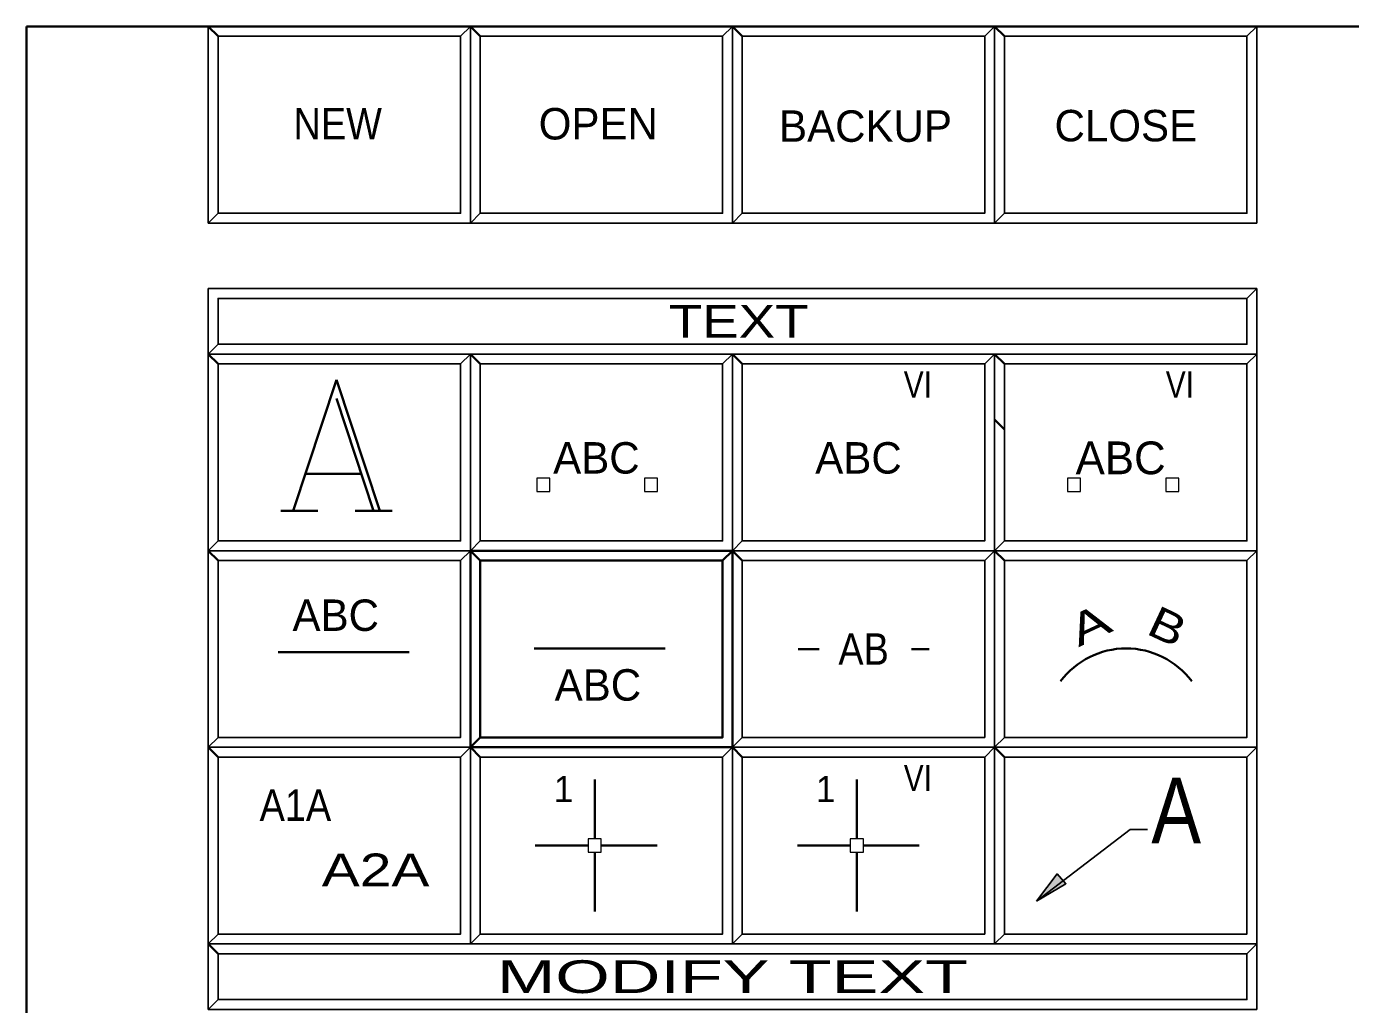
# Model space of a CAD drawing. Extents: x 95906.9 to 95918.9, y 90964.8 to 90972.9.
# Drawn here: x 95906.855 to 95908.876, y 90971.369 to 90972.862 of the extents above; entities that cross this region are included whole.
import ezdxf
from ezdxf.enums import TextEntityAlignment as Align

# ---------------------------------------------------------------- set-up
doc = ezdxf.new("R2010")
doc.units = 0
doc.header["$LTSCALE"] = 0.019
for name, color, linetype, lineweight in [('1', 7, 'Continuous', 25), ('11', 7, 'Continuous', 25), ('12', 7, 'Continuous', 25), ('17', 7, 'Continuous', 25), ('18', 7, 'Continuous', 25), ('2', 7, 'Continuous', 13), ('3', 7, 'Continuous', 25), ('4', 7, 'Continuous', 35), ('6', 7, 'Continuous', 35), ('7', 7, 'Continuous', 35)]:
    doc.layers.add(name, color=color, linetype=linetype, lineweight=lineweight)

msp = doc.modelspace()

# ---------------------------------------------------------------- hatches: boundary and pattern name
at = {"layer": '6'}
msp.add_hatch(color=256, dxfattribs=at).paths.add_polyline_path([(95908.3963, 90971.5268), (95908.4276, 90971.5686), (95908.4412, 90971.5534)])

# ---------------------------------------------------------------- linework, layer by layer
at = {"layer": '1'}
for points in [[(95907.1323, 90972.5617), (95907.5323, 90972.5617), (95907.5323, 90972.8617), (95907.1323, 90972.8617)], [(95907.5323, 90972.5617), (95907.9323, 90972.5617), (95907.9323, 90972.8617), (95907.5323, 90972.8617)], [(95907.9323, 90972.5617), (95908.3323, 90972.5617), (95908.3323, 90972.8617), (95907.9323, 90972.8617)], [(95908.3323, 90972.5617), (95908.7323, 90972.5617), (95908.7323, 90972.8617), (95908.3323, 90972.8617)], [(95907.1323, 90972.3617), (95908.7323, 90972.3617), (95908.7323, 90972.4617), (95907.1323, 90972.4617)], [(95907.1323, 90972.0617), (95907.5323, 90972.0617), (95907.5323, 90972.3617), (95907.1323, 90972.3617)], [(95907.5323, 90972.0617), (95907.9323, 90972.0617), (95907.9323, 90972.3617), (95907.5323, 90972.3617)], [(95907.9323, 90972.0617), (95908.3323, 90972.0617), (95908.3323, 90972.3617), (95907.9323, 90972.3617)], [(95908.3323, 90972.0617), (95908.7323, 90972.0617), (95908.7323, 90972.3617), (95908.3323, 90972.3617)], [(95907.1323, 90971.7617), (95907.5323, 90971.7617), (95907.5323, 90972.0617), (95907.1323, 90972.0617)], [(95907.5323, 90971.7617), (95907.9323, 90971.7617), (95907.9323, 90972.0617), (95907.5323, 90972.0617)], [(95907.9323, 90971.7617), (95908.3323, 90971.7617), (95908.3323, 90972.0617), (95907.9323, 90972.0617)], [(95908.3323, 90971.7617), (95908.7323, 90971.7617), (95908.7323, 90972.0617), (95908.3323, 90972.0617)], [(95907.1323, 90971.4617), (95907.5323, 90971.4617), (95907.5323, 90971.7617), (95907.1323, 90971.7617)], [(95907.5323, 90971.4617), (95907.9323, 90971.4617), (95907.9323, 90971.7617), (95907.5323, 90971.7617)], [(95907.9323, 90971.4617), (95908.3323, 90971.4617), (95908.3323, 90971.7617), (95907.9323, 90971.7617)], [(95908.3323, 90971.4617), (95908.7323, 90971.4617), (95908.7323, 90971.7617), (95908.3323, 90971.7617)], [(95907.1323, 90971.3617), (95908.7323, 90971.3617), (95908.7323, 90971.4617), (95907.1323, 90971.4617)]]:
    msp.add_lwpolyline(points, close=True, dxfattribs=at)
at = {"layer": '11'}
for points in [[(95907.1473, 90972.5767), (95907.5173, 90972.5767), (95907.5173, 90972.8467), (95907.1473, 90972.8467)], [(95907.5473, 90972.5767), (95907.9173, 90972.5767), (95907.9173, 90972.8467), (95907.5473, 90972.8467)], [(95907.9473, 90972.5767), (95908.3173, 90972.5767), (95908.3173, 90972.8467), (95907.9473, 90972.8467)], [(95908.3473, 90972.5767), (95908.7173, 90972.5767), (95908.7173, 90972.8467), (95908.3473, 90972.8467)], [(95907.1473, 90972.0767), (95907.5173, 90972.0767), (95907.5173, 90972.3467), (95907.1473, 90972.3467)], [(95907.5473, 90972.0767), (95907.9173, 90972.0767), (95907.9173, 90972.3467), (95907.5473, 90972.3467)], [(95907.9473, 90972.0767), (95908.3173, 90972.0767), (95908.3173, 90972.3467), (95907.9473, 90972.3467)], [(95908.3473, 90972.0767), (95908.7173, 90972.0767), (95908.7173, 90972.3467), (95908.3473, 90972.3467)], [(95907.1473, 90971.7767), (95907.5173, 90971.7767), (95907.5173, 90972.0467), (95907.1473, 90972.0467)], [(95907.9473, 90971.7767), (95908.3173, 90971.7767), (95908.3173, 90972.0467), (95907.9473, 90972.0467)], [(95908.3473, 90971.7767), (95908.7173, 90971.7767), (95908.7173, 90972.0467), (95908.3473, 90972.0467)], [(95907.1473, 90971.4767), (95907.5173, 90971.4767), (95907.5173, 90971.7467), (95907.1473, 90971.7467)], [(95907.5473, 90971.4767), (95907.9173, 90971.4767), (95907.9173, 90971.7467), (95907.5473, 90971.7467)], [(95907.9473, 90971.4767), (95908.3173, 90971.4767), (95908.3173, 90971.7467), (95907.9473, 90971.7467)], [(95908.3473, 90971.4767), (95908.7173, 90971.4767), (95908.7173, 90971.7467), (95908.3473, 90971.7467)]]:
    msp.add_lwpolyline(points, close=True, dxfattribs=at)
at = {"layer": '11', "lineweight": 35}
msp.add_lwpolyline([(95907.5473, 90971.7767), (95907.9173, 90971.7767), (95907.9173, 90972.0467), (95907.5473, 90972.0467)], close=True, dxfattribs=at)
at = {"layer": '12'}
msp.add_lwpolyline([(95907.1473, 90972.0767), (95907.5173, 90972.0767), (95907.5173, 90972.3467), (95907.1473, 90972.3467)], close=True, dxfattribs=at)
at = {"layer": '17'}
msp.add_lwpolyline([(95907.1473, 90972.3767), (95908.7173, 90972.3767), (95908.7173, 90972.4467), (95907.1473, 90972.4467)], close=True, dxfattribs=at)
at = {"layer": '18'}
msp.add_lwpolyline([(95907.1473, 90971.3767), (95908.7173, 90971.3767), (95908.7173, 90971.4467), (95907.1473, 90971.4467)], close=True, dxfattribs=at)
at = {"layer": '2'}
for points in [[(95907.1323, 90972.8617), (95907.1323, 90972.5617), (95907.1473, 90972.5767), (95907.1473, 90972.8467), (95907.5173, 90972.8467), (95907.5323, 90972.8617)], [(95907.5323, 90972.8617), (95907.5323, 90972.5617), (95907.5473, 90972.5767), (95907.5473, 90972.8467), (95907.9173, 90972.8467), (95907.9323, 90972.8617)], [(95907.9323, 90972.8617), (95907.9323, 90972.5617), (95907.9473, 90972.5767), (95907.9473, 90972.8467), (95908.3173, 90972.8467), (95908.3323, 90972.8617)], [(95908.3323, 90972.8617), (95908.3323, 90972.5617), (95908.3473, 90972.5767), (95908.3473, 90972.8467), (95908.7173, 90972.8467), (95908.7323, 90972.8617)], [(95907.1323, 90972.4617), (95907.1323, 90972.3617), (95907.1473, 90972.3767), (95907.1473, 90972.4467), (95908.7173, 90972.4467), (95908.7323, 90972.4617)], [(95907.1323, 90972.3617), (95907.1323, 90972.0617), (95907.1473, 90972.0767), (95907.1473, 90972.3467), (95907.5173, 90972.3467), (95907.5323, 90972.3617)], [(95907.5323, 90972.3617), (95907.5323, 90972.0617), (95907.5473, 90972.0767), (95907.5473, 90972.3467), (95907.9173, 90972.3467), (95907.9323, 90972.3617)], [(95907.9323, 90972.3617), (95907.9323, 90972.0617), (95907.9473, 90972.0767), (95907.9473, 90972.3467), (95908.3173, 90972.3467), (95908.3323, 90972.3617)], [(95908.3323, 90972.3617), (95908.3323, 90972.0617), (95908.3473, 90972.0767), (95908.3473, 90972.3467), (95908.7173, 90972.3467), (95908.7323, 90972.3617)], [(95907.1323, 90972.0617), (95907.1323, 90971.7617), (95907.1473, 90971.7767), (95907.1473, 90972.0467), (95907.5173, 90972.0467), (95907.5323, 90972.0617)], [(95907.9323, 90972.0617), (95907.9323, 90971.7617), (95907.9473, 90971.7767), (95907.9473, 90972.0467), (95908.3173, 90972.0467), (95908.3323, 90972.0617)], [(95908.3323, 90972.0617), (95908.3323, 90971.7617), (95908.3473, 90971.7767), (95908.3473, 90972.0467), (95908.7173, 90972.0467), (95908.7323, 90972.0617)], [(95907.1323, 90971.7617), (95907.1323, 90971.4617), (95907.1473, 90971.4767), (95907.1473, 90971.7467), (95907.5173, 90971.7467), (95907.5323, 90971.7617)], [(95907.5323, 90971.7617), (95907.5323, 90971.4617), (95907.5473, 90971.4767), (95907.5473, 90971.7467), (95907.9173, 90971.7467), (95907.9323, 90971.7617)], [(95907.9323, 90971.7617), (95907.9323, 90971.4617), (95907.9473, 90971.4767), (95907.9473, 90971.7467), (95908.3173, 90971.7467), (95908.3323, 90971.7617)], [(95908.3323, 90971.7617), (95908.3323, 90971.4617), (95908.3473, 90971.4767), (95908.3473, 90971.7467), (95908.7173, 90971.7467), (95908.7323, 90971.7617)], [(95907.1323, 90971.4617), (95907.1323, 90971.3617), (95907.1473, 90971.3767), (95907.1473, 90971.4467), (95908.7173, 90971.4467), (95908.7323, 90971.4617)]]:
    msp.add_lwpolyline(points, close=True, dxfattribs=at)
at = {"layer": '2', "lineweight": 35}
msp.add_lwpolyline([(95907.5323, 90972.0617), (95907.5323, 90971.7617), (95907.5473, 90971.7767), (95907.5473, 90972.0467), (95907.9173, 90972.0467), (95907.9323, 90972.0617)], close=True, dxfattribs=at)
at = {"layer": '3'}
for points in [[(95907.1323, 90972.5617), (95907.5323, 90972.5617), (95907.5323, 90972.8617), (95907.5173, 90972.8467), (95907.5173, 90972.5767), (95907.1473, 90972.5767)], [(95907.5323, 90972.5617), (95907.9323, 90972.5617), (95907.9323, 90972.8617), (95907.9173, 90972.8467), (95907.9173, 90972.5767), (95907.5473, 90972.5767)], [(95907.9323, 90972.5617), (95908.3323, 90972.5617), (95908.3323, 90972.8617), (95908.3173, 90972.8467), (95908.3173, 90972.5767), (95907.9473, 90972.5767)], [(95908.3323, 90972.5617), (95908.7323, 90972.5617), (95908.7323, 90972.8617), (95908.7173, 90972.8467), (95908.7173, 90972.5767), (95908.3473, 90972.5767)], [(95907.1323, 90972.3617), (95908.7323, 90972.3617), (95908.7323, 90972.4617), (95908.7173, 90972.4467), (95908.7173, 90972.3767), (95907.1473, 90972.3767)], [(95907.1323, 90972.0617), (95907.5323, 90972.0617), (95907.5323, 90972.3617), (95907.5173, 90972.3467), (95907.5173, 90972.0767), (95907.1473, 90972.0767)], [(95907.5323, 90972.0617), (95907.9323, 90972.0617), (95907.9323, 90972.3617), (95907.9173, 90972.3467), (95907.9173, 90972.0767), (95907.5473, 90972.0767)], [(95907.9323, 90972.0617), (95908.3323, 90972.0617), (95908.3323, 90972.3617), (95908.3173, 90972.3467), (95908.3173, 90972.0767), (95907.9473, 90972.0767)], [(95908.3323, 90972.0617), (95908.7323, 90972.0617), (95908.7323, 90972.3617), (95908.7173, 90972.3467), (95908.7173, 90972.0767), (95908.3473, 90972.0767)], [(95907.1323, 90971.7617), (95907.5323, 90971.7617), (95907.5323, 90972.0617), (95907.5173, 90972.0467), (95907.5173, 90971.7767), (95907.1473, 90971.7767)], [(95907.9323, 90971.7617), (95908.3323, 90971.7617), (95908.3323, 90972.0617), (95908.3173, 90972.0467), (95908.3173, 90971.7767), (95907.9473, 90971.7767)], [(95908.3323, 90971.7617), (95908.7323, 90971.7617), (95908.7323, 90972.0617), (95908.7173, 90972.0467), (95908.7173, 90971.7767), (95908.3473, 90971.7767)], [(95907.1323, 90971.4617), (95907.5323, 90971.4617), (95907.5323, 90971.7617), (95907.5173, 90971.7467), (95907.5173, 90971.4767), (95907.1473, 90971.4767)], [(95907.5323, 90971.4617), (95907.9323, 90971.4617), (95907.9323, 90971.7617), (95907.9173, 90971.7467), (95907.9173, 90971.4767), (95907.5473, 90971.4767)], [(95907.9323, 90971.4617), (95908.3323, 90971.4617), (95908.3323, 90971.7617), (95908.3173, 90971.7467), (95908.3173, 90971.4767), (95907.9473, 90971.4767)], [(95908.3323, 90971.4617), (95908.7323, 90971.4617), (95908.7323, 90971.7617), (95908.7173, 90971.7467), (95908.7173, 90971.4767), (95908.3473, 90971.4767)], [(95907.1323, 90971.3617), (95908.7323, 90971.3617), (95908.7323, 90971.4617), (95908.7173, 90971.4467), (95908.7173, 90971.3767), (95907.1473, 90971.3767)]]:
    msp.add_lwpolyline(points, close=True, dxfattribs=at)
at = {"layer": '3', "lineweight": 35}
msp.add_lwpolyline([(95907.5323, 90971.7617), (95907.9323, 90971.7617), (95907.9323, 90972.0617), (95907.9173, 90972.0467), (95907.9173, 90971.7767), (95907.5473, 90971.7767)], close=True, dxfattribs=at)
at = {"layer": '4'}
for p, q in [((95907.1473, 90972.8467), (95907.1323, 90972.8617)), ((95907.5473, 90972.8467), (95907.5323, 90972.8617)), ((95907.9473, 90972.8467), (95907.9323, 90972.8617)), ((95908.3473, 90972.8467), (95908.3323, 90972.8617)), ((95907.1473, 90972.3467), (95907.1323, 90972.3617)), ((95907.1473, 90972.3467), (95907.1323, 90972.3617)), ((95907.5473, 90972.3467), (95907.5323, 90972.3617)), ((95907.9473, 90972.3467), (95907.9323, 90972.3617)), ((95908.3473, 90972.3467), (95908.3323, 90972.3617)), ((95908.3473, 90972.2467), (95908.3323, 90972.2617)), ((95907.1473, 90972.0467), (95907.1323, 90972.0617)), ((95907.5473, 90972.0467), (95907.5323, 90972.0617)), ((95907.9473, 90972.0467), (95907.9323, 90972.0617)), ((95908.3473, 90972.0467), (95908.3323, 90972.0617)), ((95907.1473, 90971.7467), (95907.1323, 90971.7617)), ((95907.5473, 90971.7467), (95907.5323, 90971.7617)), ((95907.9473, 90971.7467), (95907.9323, 90971.7617)), ((95908.3473, 90971.7467), (95908.3323, 90971.7617)), ((95907.1473, 90971.4467), (95907.1323, 90971.4617))]:
    msp.add_line(p, q, dxfattribs=at)
at = {"layer": '6'}
for p, q in [((95907.3278, 90972.3225), (95907.2617, 90972.1225)), ((95907.3278, 90972.3225), (95907.394, 90972.1225)), ((95907.3278, 90972.2942), (95907.3845, 90972.1225)), ((95907.2806, 90972.1792), (95907.3656, 90972.1792)), ((95907.2428, 90972.1225), (95907.2995, 90972.1225)), ((95907.3562, 90972.1225), (95907.4129, 90972.1225)), ((95907.6297, 90971.9127), (95907.8297, 90971.9127)), ((95908.0323, 90971.9117), (95908.0648, 90971.9117)), ((95908.2323, 90971.9117), (95908.2054, 90971.9117)), ((95907.239, 90971.9071), (95907.439, 90971.9071)), ((95907.7221, 90971.6218), (95907.7221, 90971.7124)), ((95908.1221, 90971.6218), (95908.1221, 90971.7124)), ((95907.7121, 90971.6118), (95907.6313, 90971.6118)), ((95907.7321, 90971.6118), (95907.8171, 90971.6118)), ((95908.1121, 90971.6118), (95908.0313, 90971.6118)), ((95908.1321, 90971.6118), (95908.2171, 90971.6118)), ((95907.7221, 90971.5112), (95907.7221, 90971.6018)), ((95908.1221, 90971.5112), (95908.1221, 90971.6018))]:
    msp.add_line(p, q, dxfattribs=at)
at = {"layer": '6', "lineweight": 13}
for points in [[(95907.6336, 90972.1522), (95907.6536, 90972.1522), (95907.6536, 90972.1722), (95907.6336, 90972.1722)], [(95907.7979, 90972.1522), (95907.8179, 90972.1522), (95907.8179, 90972.1722), (95907.7979, 90972.1722)], [(95908.4434, 90972.1522), (95908.4634, 90972.1522), (95908.4634, 90972.1722), (95908.4434, 90972.1722)], [(95908.5935, 90972.1522), (95908.6135, 90972.1522), (95908.6135, 90972.1722), (95908.5935, 90972.1722)], [(95907.7121, 90971.6018), (95907.7321, 90971.6018), (95907.7321, 90971.6218), (95907.7121, 90971.6218)], [(95908.1121, 90971.6018), (95908.1321, 90971.6018), (95908.1321, 90971.6218), (95908.1121, 90971.6218)]]:
    msp.add_lwpolyline(points, close=True, dxfattribs=at)
at = {"layer": '6', "lineweight": 25}
msp.add_lwpolyline([(95908.5659, 90971.6364), (95908.539, 90971.6364), (95908.3963, 90971.5268)], dxfattribs=at)
msp.add_lwpolyline([(95908.3963, 90971.5268), (95908.4276, 90971.5686), (95908.4412, 90971.5534)], close=True, dxfattribs=at)
at = {"layer": '6'}
msp.add_arc((95908.5331, 90971.7876), 0.125, 36.8699, 143.1301, dxfattribs=at)
at = {"layer": '7'}
msp.add_lwpolyline([(95906.8548, 90972.8617), (95918.8548, 90972.8617), (95918.8548, 90964.7617), (95906.8548, 90964.7617)], close=True, dxfattribs=at)

# ---------------------------------------------------------------- texts
at = {"layer": '6'}
for s, height, width, p in [('NEW', 0.048, 0.9, (95907.3298, 90972.6893)), ('NEW', 0.048, 0.9, (95907.3298, 90972.6893)), ('NEW', 0.048, 0.9, (95907.3298, 90972.6893)), ('VI', 0.04, 0.85, (95908.2152, 90972.2953)), ('VI', 0.04, 0.85, (95908.6151, 90972.2953)), ('AB', 0.048, 0.9, (95908.1324, 90971.8877)), ('VI', 0.04, 0.85, (95908.2152, 90971.6948)), ('A', 0.1, 0.85, (95908.6095, 90971.6154)), ('A1A', 0.048, 0.9, (95907.2652, 90971.6494)), (' A2A', 0.05, 1.3, (95907.3755, 90971.5496))]:
    msp.add_text(s, height=height, dxfattribs=dict(at, width=width)).set_placement(p, align=Align.CENTER)
for s, height, p in [('OPEN', 0.048, (95907.7275, 90972.6893)), ('BACKUP', 0.048, (95908.1353, 90972.6857)), ('CLOSE', 0.048, (95908.5326, 90972.6864)), ('ABC', 0.048, (95907.7246, 90972.1794)), ('ABC', 0.048, (95908.1246, 90972.1794)), ('ABC', 0.04999, (95908.5247, 90972.1784)), ('ABC', 0.048, (95907.3268, 90971.9393)), ('ABC', 0.048, (95907.7269, 90971.8329)), ('1', 0.04, (95907.6745, 90971.6781)), ('1', 0.04, (95908.0745, 90971.6781))]:
    msp.add_text(s, height=height, dxfattribs=at).set_placement(p, align=Align.CENTER)
for s, rotation, width, p in [('A', 25, 1.4, (95908.4877, 90971.927)), ('B', 335, 1.25, (95908.5861, 90971.9244))]:
    msp.add_text(s, height=0.048, rotation=rotation, dxfattribs=dict(at, width=width)).set_placement(p, align=Align.CENTER)
at = {"layer": '7'}
for s, height, width, p in [('TEXT', 0.05, 1.25, (95907.9417, 90972.3867)), ('      MODIFY TEXT      ', 0.04999, 1.6, (95907.9322, 90971.3867))]:
    msp.add_text(s, height=height, dxfattribs=dict(at, width=width)).set_placement(p, align=Align.CENTER)

doc.saveas('drawing.dxf')
